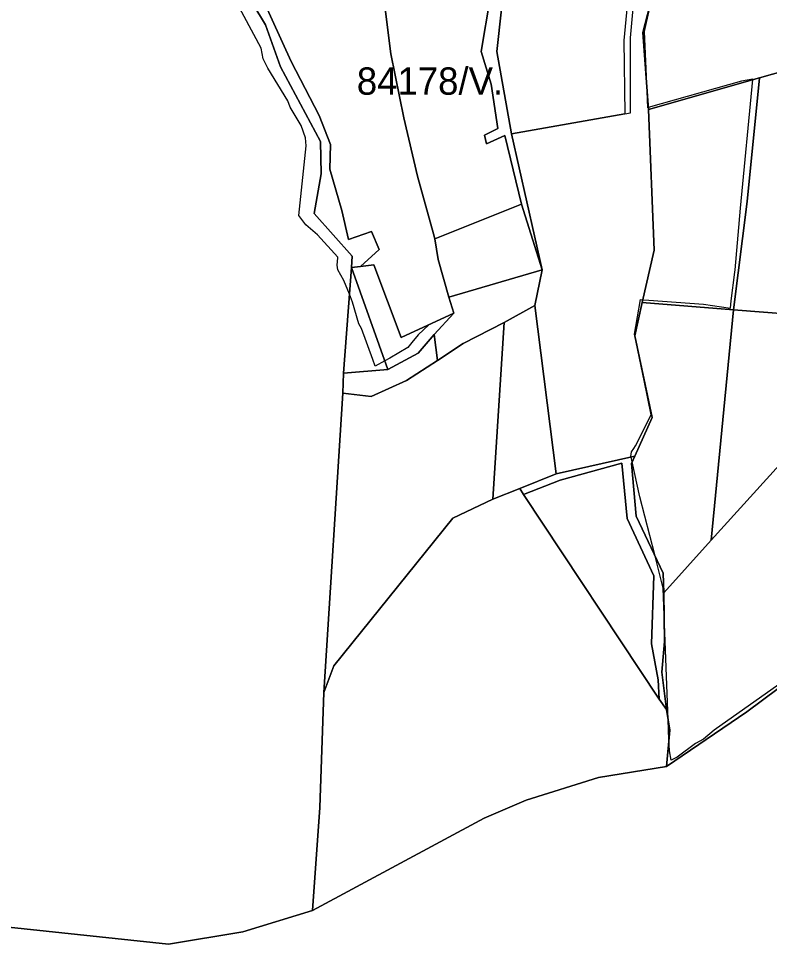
# Model space of a CAD drawing. Extents: x -477304 to -465429, y -1159113 to -1149210.
# Drawn here: x -472801 to -472389, y -1154555 to -1154043 of the extents above; entities that cross this region are included whole.
import ezdxf

# ---------------------------------------------------------------- set-up
doc = ezdxf.new("R2010")
doc.units = 0
for name, color, linetype in [('BPEJ_s', 7, 'Continuous'), ('PUPFL_s', 7, 'Continuous'), ('trav_porost_s', 7, 'Continuous')]:
    doc.layers.add(name, color=color, linetype=linetype)

msp = doc.modelspace()

# ---------------------------------------------------------------- linework, layer by layer
at = {"layer": 'BPEJ_s'}
for points in [[(-472528.59, -1153971.02), (-472538.45, -1154060.94), (-472530.52, -1154106.09), (-472513.63, -1154180.72), (-472525.05, -1154144.76), (-472572.62, -1154163.71), (-472570.69, -1154175.01), (-472564.9, -1154195.68), (-472562.1, -1154204.59), (-472575.93, -1154210.94), (-472581.73, -1154216.39), (-472585.21, -1154220.65), (-472587.46, -1154223.41), (-472597.25, -1154229.15), (-472600, -1154230.66), (-472605.31, -1154233.57), (-472606.6, -1154230), (-472612.77, -1154212.99), (-472614.26, -1154210.44), (-472617.66, -1154198.53), (-472619.46, -1154194.14), (-472622.55, -1154186.62), (-472625.74, -1154180.67), (-472626.17, -1154178.12), (-472625.78, -1154174.24), (-472625.74, -1154173.87), (-472637.01, -1154161.53), (-472643.39, -1154156), (-472647.22, -1154150.9), (-472643.18, -1154112.63), (-472643.6, -1154108.37), (-472645.94, -1154101.57), (-472651.9, -1154091.36), (-472653.17, -1154087.96), (-472664.23, -1154070.1), (-472666.78, -1154064.99), (-472667.84, -1154059.04), (-472686.56, -1154024.17)], [(-472528.59, -1153971.02), (-472538.45, -1154060.94), (-472530.52, -1154106.09), (-472513.63, -1154180.72), (-472525.05, -1154144.76), (-472572.62, -1154163.71), (-472570.69, -1154175.01), (-472564.9, -1154195.68), (-472562.1, -1154204.59), (-472575.93, -1154210.94), (-472581.73, -1154216.39), (-472585.21, -1154220.65), (-472587.46, -1154223.41), (-472597.25, -1154229.15), (-472600, -1154230.66), (-472605.31, -1154233.57), (-472606.6, -1154230), (-472612.77, -1154212.99), (-472614.26, -1154210.44), (-472617.66, -1154198.53), (-472619.46, -1154194.14), (-472622.55, -1154186.62), (-472625.74, -1154180.67), (-472626.17, -1154178.12), (-472625.78, -1154174.24), (-472625.74, -1154173.87), (-472637.01, -1154161.53), (-472643.39, -1154156), (-472647.22, -1154150.9), (-472643.18, -1154112.63), (-472643.6, -1154108.37), (-472645.94, -1154101.57), (-472651.9, -1154091.36), (-472653.17, -1154087.96), (-472664.23, -1154070.1), (-472666.78, -1154064.99), (-472667.84, -1154059.04), (-472686.56, -1154024.17)], [(-472383.73, -1154408.33), (-472419.22, -1154433.47), (-472425.17, -1154438.36), (-472429.42, -1154440.69), (-472439.62, -1154448.34), (-472442.81, -1154449.83), (-472443.87, -1154444.73), (-472444.11, -1154438.57), (-472444.52, -1154427.69), (-472446.71, -1154370.27), (-472447.27, -1154355.49), (-472451.91, -1154337.24), (-472460.02, -1154305.35), (-472464.25, -1154286.23), (-472464.85, -1154283.52), (-472464.91, -1154283.25), (-472464.69, -1154280.7), (-472463.36, -1154278.76), (-472462.36, -1154277.3), (-472453.86, -1154260.3), (-472457.75, -1154241.45), (-472462.99, -1154216.1), (-472459.67, -1154197.08), (-472458.48, -1154197.17), (-472455.13, -1154197.41), (-472425.17, -1154199.53), (-472410.36, -1154201.74), (-472409.87, -1154197.83), (-472407.91, -1154182.07), (-472407.75, -1154180.83), (-472404.78, -1154146.84), (-472398.08, -1154076.34), (-472398.05, -1154076.05), (-472404.35, -1154077.14), (-472455.45, -1154091.71), (-472455.71, -1154091.78), (-472456.09, -1154082.68), (-472457.47, -1154049.95), (-472452.3, -1154026.77)], [(-472462.99, -1154216.1), (-472459.67, -1154197.08), (-472458.48, -1154197.17), (-472455.13, -1154197.41), (-472425.17, -1154199.53), (-472410.36, -1154201.74), (-472409.87, -1154197.83), (-472407.91, -1154182.07), (-472407.75, -1154180.83), (-472404.78, -1154146.84), (-472398.08, -1154076.34), (-472398.05, -1154076.05), (-472404.35, -1154077.14), (-472455.45, -1154091.71), (-472455.71, -1154091.78), (-472456.09, -1154082.68), (-472457.47, -1154049.95), (-472452.3, -1154026.77)], [(-472383.73, -1154408.33), (-472419.22, -1154433.47), (-472425.17, -1154438.36), (-472429.42, -1154440.69), (-472439.62, -1154448.34), (-472442.81, -1154449.83), (-472443.87, -1154444.73), (-472444.11, -1154438.57), (-472444.52, -1154427.69), (-472446.71, -1154370.27), (-472447.27, -1154355.49), (-472451.91, -1154337.24), (-472460.02, -1154305.35), (-472464.25, -1154286.23), (-472464.85, -1154283.52), (-472464.91, -1154283.25), (-472464.69, -1154280.7), (-472463.36, -1154278.76), (-472462.36, -1154277.3), (-472453.86, -1154260.3), (-472457.75, -1154241.45), (-472462.99, -1154216.1)]]:
    msp.add_lwpolyline(points, dxfattribs=at)
at = {"layer": 'PUPFL_s'}
for points in [[(-472458.42, -1153888.26), (-472456.78, -1153884.15), (-472439.98, -1153867.43), (-472437.22, -1153927.39), (-472440.92, -1153982.01), (-472446.75, -1154005.15), (-472458.38, -1154050.48), (-472455.38, -1154092.67), (-472452.22, -1154169.89), (-472458.83, -1154198.7), (-472462.78, -1154216.95), (-472453.33, -1154261.75), (-472462.8, -1154283.06), (-472506.01, -1154292.72), (-472517.7, -1154200.33), (-472513.63, -1154180.72), (-472530.52, -1154106.09), (-472468.28, -1154095.1), (-472465.12, -1154094.54), (-472465.12, -1154053.36), (-472458.54, -1153980.69)], [(-472530.52, -1154106.09), (-472538.45, -1154060.94), (-472528.59, -1153971.02), (-472461.62, -1153979.81), (-472468.89, -1154054.81), (-472468.28, -1154095.1)], [(-472434.57, -1154008.93), (-472362.09, -1154031.45), (-472335.92, -1153986.24), (-472335.63, -1154034.49), (-472333.49, -1154058.22), (-472394.38, -1154075.28), (-472455.38, -1154092.67), (-472458.38, -1154050.48), (-472446.75, -1154005.15)], [(-472401.16, -1154143.14), (-472394.38, -1154075.28), (-472333.49, -1154058.22), (-472331.73, -1154057.73), (-472332.26, -1154061.8), (-472362.17, -1154186), (-472361.66, -1154206.28), (-472408.66, -1154202.61)], [(-472394.38, -1154075.28), (-472401.16, -1154143.14), (-472408.66, -1154202.61), (-472458.83, -1154198.7), (-472452.22, -1154169.89), (-472455.38, -1154092.67)], [(-472570.69, -1154175.01), (-472572.62, -1154163.71), (-472525.05, -1154144.76), (-472513.63, -1154180.72), (-472564.9, -1154195.68)], [(-472598.3, -1154235.42), (-472622.78, -1154237.39), (-472618.34, -1154179.49)], [(-472618.34, -1154179.49), (-472613.45, -1154178.87), (-472606.1, -1154177.93), (-472591.09, -1154217.9), (-472562.1, -1154204.59), (-472572.95, -1154216.31), (-472581.78, -1154226.42), (-472598.3, -1154235.42)], [(-472571.18, -1154230.49), (-472572.95, -1154216.31), (-472562.1, -1154204.59), (-472564.9, -1154195.68), (-472513.63, -1154180.72), (-472517.7, -1154200.33), (-472534.54, -1154209.69), (-472557.09, -1154221.24)], [(-472534.54, -1154209.69), (-472517.7, -1154200.33), (-472506.01, -1154292.72), (-472525.94, -1154300.77), (-472540.75, -1154306.65)], [(-472453.33, -1154261.75), (-472462.78, -1154216.95), (-472458.83, -1154198.7), (-472408.66, -1154202.61), (-472420.83, -1154329.2), (-472446.86, -1154358.02), (-472447.19, -1154347.21), (-472462.02, -1154315.9), (-472464.6, -1154287), (-472462.8, -1154283.06)], [(-472361.08, -1154225.07), (-472360.26, -1154262.14), (-472420.83, -1154329.2), (-472408.66, -1154202.61), (-472361.66, -1154206.28)], [(-472588.19, -1154241.54), (-472571.18, -1154230.49), (-472557.09, -1154221.24), (-472534.54, -1154209.69), (-472540.75, -1154306.65), (-472562.68, -1154317.09), (-472627.92, -1154398.05), (-472633.5, -1154412.68), (-472623.07, -1154248.49), (-472607.42, -1154250.34)], [(-472598.3, -1154235.42), (-472581.78, -1154226.42), (-472572.95, -1154216.31), (-472571.18, -1154230.49), (-472588.19, -1154241.54), (-472607.42, -1154250.34), (-472623.07, -1154248.49), (-472622.78, -1154237.39)], [(-472445.38, -1154422.01), (-472447.92, -1154401.59), (-472446.53, -1154384.74), (-472446.86, -1154358.02), (-472420.83, -1154329.2), (-472360.26, -1154262.14), (-472384.09, -1154410.55), (-472401.42, -1154423.45), (-472445.42, -1154453.37), (-472443.65, -1154433.44)], [(-472445.38, -1154422.01), (-472449.51, -1154416.38), (-472449.98, -1154405.9), (-472453.63, -1154386.05), (-472452.36, -1154348.77), (-472466.94, -1154317.29), (-472469.9, -1154286.92), (-472503.75, -1154296.21), (-472523.88, -1154304.06), (-472525.94, -1154300.77), (-472506.01, -1154292.72), (-472462.8, -1154283.06), (-472464.6, -1154287), (-472462.02, -1154315.9), (-472447.19, -1154347.21), (-472446.86, -1154358.02), (-472446.53, -1154384.74), (-472447.92, -1154401.59)], [(-472469.9, -1154286.92), (-472466.94, -1154317.29), (-472452.36, -1154348.77), (-472453.63, -1154386.05), (-472449.98, -1154405.9), (-472449.51, -1154416.38), (-472523.88, -1154304.06), (-472503.75, -1154296.21)], [(-472525.94, -1154300.77), (-472523.88, -1154304.06), (-472449.51, -1154416.38), (-472445.38, -1154422.01), (-472443.65, -1154433.44), (-472445.42, -1154453.37), (-472482.74, -1154459.45), (-472522.51, -1154471.95), (-472545.51, -1154481.81), (-472639.66, -1154532.36), (-472635.69, -1154475.83), (-472633.5, -1154412.68), (-472627.92, -1154398.05), (-472562.68, -1154317.09), (-472540.75, -1154306.65)]]:
    msp.add_lwpolyline(points, close=True, dxfattribs=at)
for points in [[(-472809.81, -1153986.28), (-472787.72, -1154000.44), (-472781.1, -1154004.49), (-472767.03, -1154003.2), (-472766.27, -1154006.69), (-472762.01, -1154026.14), (-472703.7, -1154020.01), (-472685.24, -1154018.18), (-472679.32, -1154022.97), (-472665.52, -1154046.23), (-472657.33, -1154069.24), (-472635.34, -1154110.22), (-472635.02, -1154127.99), (-472638.86, -1154149.74), (-472618.01, -1154173.32), (-472618.34, -1154179.49), (-472622.78, -1154237.39), (-472623.07, -1154248.49), (-472633.5, -1154412.68), (-472635.69, -1154475.83), (-472639.66, -1154532.36), (-472678.01, -1154544.18), (-472718.68, -1154550.96), (-472836.02, -1154538.48)], [(-472829.82, -1154575.42), (-472845.56, -1154551.84), (-472836.02, -1154538.48), (-472718.68, -1154550.96), (-472678.01, -1154544.18), (-472639.66, -1154532.36), (-472545.51, -1154481.81), (-472522.51, -1154471.95), (-472482.74, -1154459.45), (-472445.42, -1154453.37), (-472401.42, -1154423.45), (-472384.09, -1154410.55), (-472379.28, -1154406.61), (-472329.41, -1154411.16), (-472150.64, -1154427.27), (-472018.16, -1154439.35), (-472022.72, -1154458.3), (-471976.15, -1154460.64), (-471961.55, -1154462.05), (-471926.3, -1154475.13), (-471912.68, -1154523.9), (-471906.1, -1154578.81)]]:
    msp.add_lwpolyline(points, dxfattribs=at)
at = {"layer": 'trav_porost_s'}
for points in [[(-472538.77, -1153903.52), (-472532.25, -1153931.35), (-472528.59, -1153971.02), (-472538.45, -1154060.94), (-472530.52, -1154106.09), (-472513.63, -1154180.72), (-472525.05, -1154144.76), (-472534.13, -1154107.04), (-472544.23, -1154111.56), (-472545.36, -1154106.84), (-472537.98, -1154103.11), (-472541.57, -1154078.78), (-472547.08, -1154060.89), (-472532.33, -1153972.86), (-472536.32, -1153934.3), (-472542.68, -1153905.09)], [(-472609.2, -1153970.72), (-472587.7, -1153958.11), (-472599.42, -1153927.91), (-472542.68, -1153905.09), (-472536.32, -1153934.3), (-472532.33, -1153972.86), (-472547.08, -1154060.89), (-472541.57, -1154078.78), (-472537.98, -1154103.11), (-472545.36, -1154106.84), (-472544.23, -1154111.56), (-472534.13, -1154107.04), (-472525.05, -1154144.76), (-472572.62, -1154163.71), (-472573.26, -1154160.94), (-472582.03, -1154129.27), (-472589.55, -1154097.38), (-472596.73, -1154062.16), (-472603.59, -1154006.47), (-472609.63, -1153975.68)]]:
    msp.add_lwpolyline(points, close=True, dxfattribs=at)
for points in [[(-472603.59, -1154006.47), (-472596.73, -1154062.16), (-472589.55, -1154097.38), (-472582.03, -1154129.27), (-472573.26, -1154160.94), (-472572.62, -1154163.71), (-472570.69, -1154175.01), (-472564.9, -1154195.68), (-472562.1, -1154204.59), (-472591.09, -1154217.9), (-472606.1, -1154177.93), (-472613.45, -1154178.87), (-472603.04, -1154169.65), (-472607.33, -1154159.62), (-472619.87, -1154164.04), (-472623.58, -1154148.09), (-472630.14, -1154125.46), (-472629.76, -1154112.03), (-472636.12, -1154096.08), (-472651.5, -1154066.33), (-472673.27, -1154018.5)], [(-472673.27, -1154018.5), (-472651.5, -1154066.33), (-472636.12, -1154096.08), (-472629.76, -1154112.03), (-472630.14, -1154125.46), (-472623.58, -1154148.09), (-472619.87, -1154164.04), (-472607.33, -1154159.62), (-472603.04, -1154169.65), (-472613.45, -1154178.87), (-472618.34, -1154179.49), (-472618.01, -1154173.32), (-472638.86, -1154149.74), (-472635.02, -1154127.99), (-472635.34, -1154110.22), (-472657.33, -1154069.24), (-472665.52, -1154046.23), (-472679.32, -1154022.97)]]:
    msp.add_lwpolyline(points, dxfattribs=at)

# ---------------------------------------------------------------- texts
at = {"layer": 'BPEJ_s'}
msp.add_text('84178/V.', height=15, dxfattribs=at).set_placement((-472615.38, -1154084.61))

doc.saveas('drawing.dxf')
